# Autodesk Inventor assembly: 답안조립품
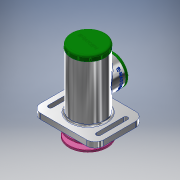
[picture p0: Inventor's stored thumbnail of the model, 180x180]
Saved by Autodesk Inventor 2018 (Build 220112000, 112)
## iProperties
Created: 2021-07
Part Number: 답안조립품
Document SubType Name: Assembly
Designer: 1class13
Author: 1class13
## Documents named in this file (20)
- C:\Users\1class13\Desktop\710706V1025\답안조립품.iam
- C:\Users\1class13\Desktop\710706V1025\본체.ipt
- C:\Users\1class13\Desktop\710706V1025\축.ipt
- C:\Users\1class13\Desktop\710706V1025\부시1.ipt
- C:\Users\1class13\Desktop\710706V1025\베어링 15 x 35 x 11.ipt
- C:\Users\1class13\Desktop\710706V1025\멈춤링 35 x 1.6.ipt
- C:\Users\1class13\Desktop\710706V1025\부시2.ipt
- C:\Users\1class13\Desktop\710706V1025\멈춤링 15 x 1.ipt
- C:\Users\1class13\Desktop\710706V1025\와셔 10 x 21.ipt
- C:\Users\1class13\Desktop\710706V1025\너트 M10.ipt
- C:\Users\1class13\Desktop\710706V1025\사이드 커버.ipt
- 사이드 커버.ipt
- C:\Users\1class13\Desktop\710706V1025\오일 실 15 25 7.ipt
- C:\Users\1class13\Desktop\710706V1025\키 4 x 4 x 18.ipt
- C:\Users\1class13\Desktop\710706V1025\V-벨트풀리.ipt
- C:\Users\1class13\Desktop\710706V1025\볼트 M4 x 10.ipt
- C:\Users\1class13\Desktop\710706V1025\와셔 4 x 16.ipt
- C:\Users\1class13\Desktop\710706V1025\탑 커버.ipt
- C:\Users\1class13\Desktop\710706V1025\와셔 3 x 6.ipt
- C:\Users\1class13\Desktop\710706V1025\십자볼트 M3 x 10.ipt
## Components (2 placed, 2 different names)
1. V-벨트풀리:1
2. ISO 4017 M4 x 10:1
